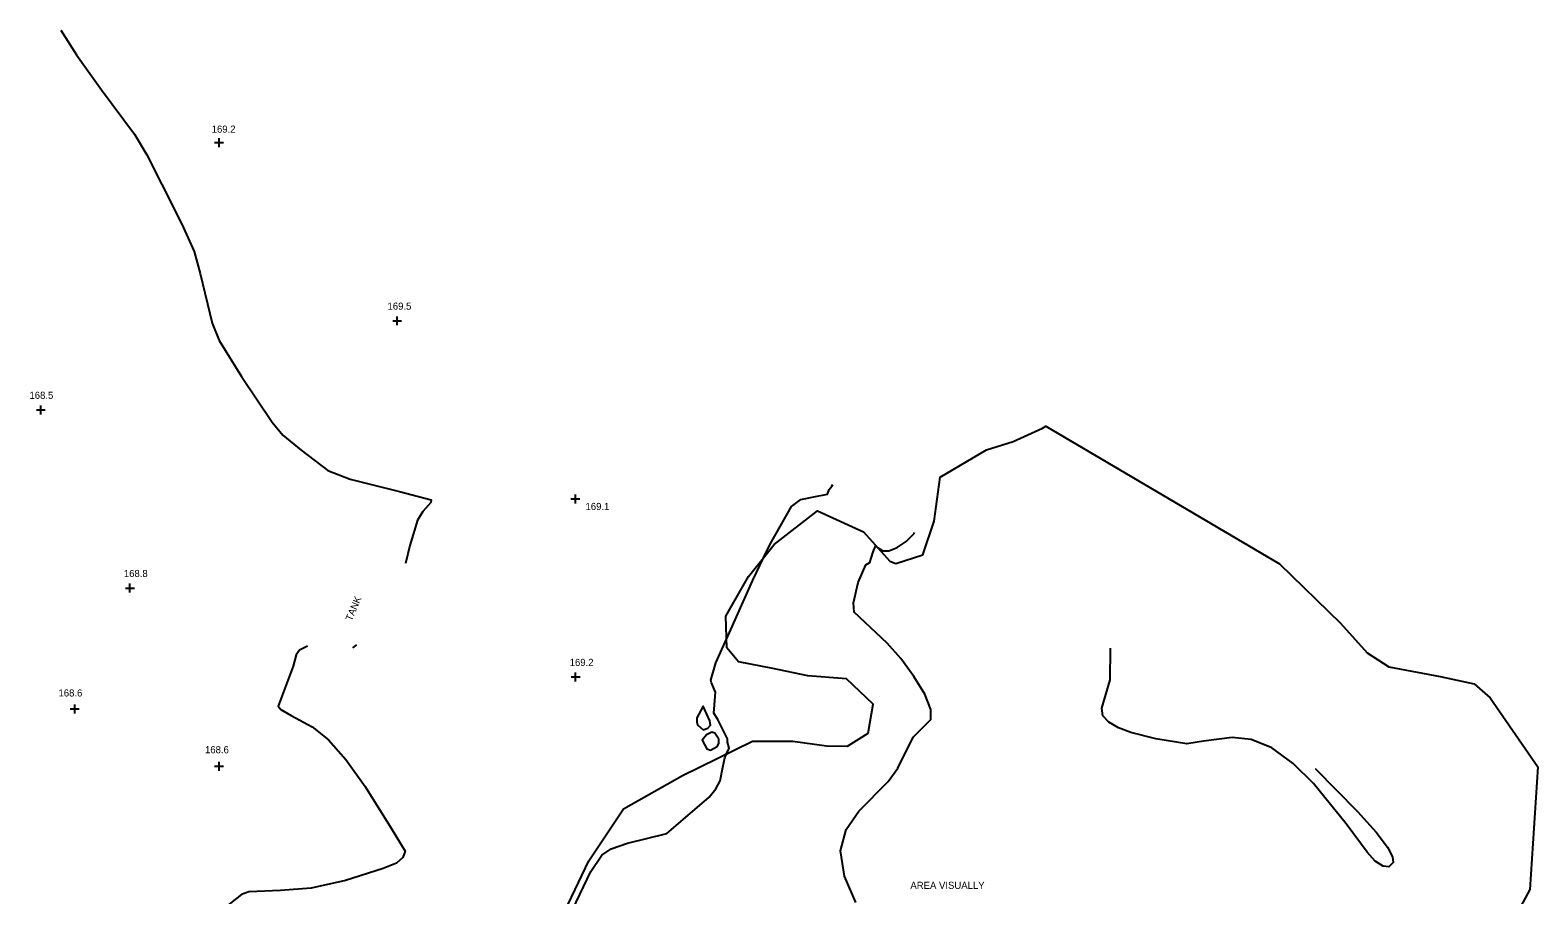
# Model space of a CAD drawing. Extents: x 1467615 to 2003689, y 770235 to 1108726.
# Drawn here: x 1998722 to 1999145.1, y 775913.9 to 776156.6 of the extents above; entities that cross this region are included whole.
import ezdxf

# ---------------------------------------------------------------- set-up
doc = ezdxf.new("R2010")
doc.units = 0
for name, color, linetype in [('RD_DTM_Major1', 7, 'Continuous'), ('RD_DTM_Minor1', 7, 'Continuous'), ('RD_DTM_Minor2', 7, 'Continuous'), ('RD_DTM_Obscure', 7, 'Continuous'), ('RD_DTM_Spot_Elev', 7, 'Continuous'), ('RD_TX_Misc1', 7, 'Continuous')]:
    doc.layers.add(name, color=color, linetype=linetype)

msp = doc.modelspace()

# ---------------------------------------------------------------- linework, layer by layer
at = {"layer": 'RD_DTM_Major1'}
for points in [[(1998909.08, 775962.46), (1998909.3, 775961.64), (1998910.88, 775960.23), (1998912.16, 775960.66), (1998912.92, 775961.54), (1998912.68, 775962.71), (1998910.89, 775966.9), (1998909.11, 775963.62), (1998909.08, 775962.46)], [(1998915.27, 775957.56), (1998914.14, 775959.25), (1998913.26, 775959.55), (1998911.76, 775958.82), (1998910.6, 775957.29), (1998911.89, 775954.92), (1998912.95, 775954.55), (1998914.81, 775955.51), (1998915.24, 775956.41), (1998915.27, 775957.56)]]:
    msp.add_lwpolyline(points, dxfattribs=at)
at = {"layer": 'RD_DTM_Minor1'}
for points in [[(1998730.64, 776156.56), (1998735.03, 776149.62), (1998741.99, 776139.85), (1998751.28, 776127.36), (1998754.76, 776121.6), (1998758.98, 776113.25), (1998764.59, 776102.1), (1998768.02, 776094.48), (1998769.75, 776088.23), (1998773.08, 776074.3), (1998775.08, 776069.49), (1998781.31, 776059.37), (1998789.91, 776046.55), (1998792.93, 776042.93), (1998798.05, 776038.7), (1998805.58, 776033.01), (1998811.79, 776030.52), (1998825.63, 776027.1), (1998834.53, 776024.74), (1998834.43, 776024.05), (1998832.16, 776021.45), (1998830.73, 776019.06), (1998828.52, 776011.95), (1998827.29, 776006.87)], [(1998927.8, 776008.52), (1998929.61, 776012.33), (1998935.68, 776022.86), (1998938.3, 776024.87), (1998941.92, 776025.64), (1998945.7, 776026.4), (1998946.23, 776027.65), (1998946.97, 776028.61), (1998947.22, 776029.05)], [(1998959.81, 776011.36), (1998961.28, 776010.43), (1998962.92, 776010.45), (1998965.25, 776011.36), (1998967.8, 776013.06), (1998970.02, 776015.36), (1998970.12, 776015.57)], [(1998917.38, 775953.46), (1998918.1, 775955.1), (1998917.72, 775956.74), (1998917.69, 775957.67), (1998915.78, 775961.48), (1998914.97, 775963.15), (1998913.84, 775964.94), (1998914.34, 775970.75), (1998913.19, 775973.45), (1998912.99, 775974.13), (1998914.39, 775978.98), (1998917.42, 775985.71)], [(1998799.86, 775983.7), (1998797.56, 775982.62), (1998796.67, 775981.26), (1998795.84, 775978.06), (1998791.62, 775966.89), (1998792.32, 775965.93), (1998795.26, 775964.29), (1998801.11, 775961.09), (1998805.73, 775957.39), (1998810.59, 775951.92), (1998815.97, 775944.28), (1998823.34, 775932.67), (1998827.22, 775926.18), (1998826.59, 775924.41), (1998824.81, 775922.84), (1998821.08, 775921.34), (1998810.47, 775917.93), (1998800.87, 775915.75), (1998792.24, 775915.18), (1998783.34, 775914.8), (1998781.34, 775914.03), (1998776.95, 775910.59)], [(1998813.57, 775984.1), (1998813.22, 775983.75), (1998812.5, 775983.19)]]:
    msp.add_lwpolyline(points, dxfattribs=at)
at = {"layer": 'RD_DTM_Minor2'}
for points in [[(1998953.66, 775911.79), (1998950.51, 775919.19), (1998949.39, 775926.23), (1998951, 775932.26), (1998954.55, 775937.36), (1998962.8, 775945.75), (1998965.46, 775949.49), (1998969.74, 775958.13), (1998974.74, 775963.11), (1998974.74, 775965.97), (1998973.02, 775970.19), (1998970, 775975.21), (1998966.28, 775980.26), (1998962.46, 775984.56), (1998953.21, 775993.26), (1998953.02, 775995.82), (1998954.32, 776001.59), (1998956.5, 776006.56), (1998957.65, 776007.22), (1998958.59, 776010.21), (1998959.23, 776011.72), (1998959.81, 776011.36)], [(1998917.42, 775985.71), (1998919.49, 775990.29), (1998924.8, 776002.19), (1998927.8, 776008.52)], [(1999082.57, 775949.37), (1999094.49, 775937.32), (1999099.73, 775931.53), (1999102.91, 775927.33), (1999104.3, 775924.6), (1999104.47, 775922.99), (1999103.26, 775921.78), (1999101.67, 775921.96), (1999099.41, 775923.39), (1999097.17, 775925.92), (1999091.23, 775933.81), (1999082.06, 775945.12), (1999076.38, 775950.82), (1999070.46, 775955.18), (1999064.66, 775957.49), (1999059.3, 775958.11), (1999051.2, 775957.01), (1999046.59, 775956.25), (1999037.85, 775957.71), (1999030.83, 775959.52), (1999027.43, 775960.79), (1999024.68, 775962.34), (1999023.03, 775964.19), (1999022.74, 775966.35), (1999025.01, 775974.25), (1999025.12, 775983.03), (1999025.19, 775983.15)], [(1998870.85, 775901.6), (1998875.18, 775911.85), (1998879.32, 775920.48), (1998882.46, 775925.06), (1998885.06, 775926.84), (1998889.58, 775928.44), (1998900.61, 775931.17), (1998905.2, 775935.03), (1998912.52, 775941.35), (1998914.45, 775943.66), (1998915.61, 775945.89), (1998916.4, 775949.79), (1998916.89, 775952.36), (1998917.38, 775953.46)]]:
    msp.add_lwpolyline(points, dxfattribs=at)
at = {"layer": 'RD_DTM_Obscure'}
for points in [[(1998872.93, 775911.34), (1998878.75, 775923.44), (1998888.53, 775938.01), (1998905.09, 775947.43), (1998924.72, 775957.06), (1998935.99, 775957.02), (1998945.48, 775955.74), (1998951.39, 775955.61), (1998957.14, 775959.31), (1998958.53, 775967.46), (1998951.08, 775974.56), (1998940.22, 775975.34), (1998930.38, 775977.41), (1998920.73, 775979.27), (1998917.5, 775983.27), (1998917.22, 775992.09), (1998923.56, 776003.22), (1998930.74, 776012.2), (1998942.93, 776021.68), (1998955.81, 776015.81), (1998963.21, 776007.56), (1998964.9, 776006.89), (1998972.5, 776009.35), (1998975.69, 776018.75), (1998977.32, 776031.12), (1998990.39, 776038.84), (1998997.8, 776041.12), (1999006.05, 776044.89), (1999007.04, 776045.41), (1999072.6, 776006.76), (1999089.72, 775990.11), (1999097.13, 775981.85), (1999103.24, 775977.88), (1999117.66, 775975.17), (1999127.14, 775973.12), (1999131.72, 775969.23), (1999145.05, 775949.81)], [(1999145.05, 775949.81), (1999142.8, 775915.4), (1999133.63, 775898.44)]]:
    msp.add_lwpolyline(points, dxfattribs=at)
at = {"layer": 'RD_DTM_Spot_Elev'}
for p, q in [((1998773.75, 776125), (1998776.25, 776125)), ((1998775, 776123.75), (1998775, 776126.25)), ((1998823.75, 776075), (1998826.25, 776075)), ((1998825, 776073.75), (1998825, 776076.25)), ((1998723.75, 776050), (1998726.25, 776050)), ((1998725, 776048.75), (1998725, 776051.25)), ((1998873.75, 776025), (1998876.25, 776025)), ((1998875, 776023.75), (1998875, 776026.25)), ((1998748.75, 776000), (1998751.25, 776000)), ((1998750, 775998.75), (1998750, 776001.25)), ((1998875.05, 775973.8), (1998875.05, 775976.3)), ((1998873.8, 775975.05), (1998876.3, 775975.05)), ((1998733.28, 775966.1), (1998735.78, 775966.1)), ((1998734.53, 775964.85), (1998734.53, 775967.35)), ((1998775, 775948.75), (1998775, 775951.25)), ((1998773.75, 775950), (1998776.25, 775950))]:
    msp.add_line(p, q, dxfattribs=at)

# ---------------------------------------------------------------- texts
for s, p in [('169.2', (1998772.95, 776127.79)), ('169.5', (1998822.28, 776078.12)), ('168.5', (1998721.81, 776053.1)), ('169.1', (1998877.84, 776021.91)), ('168.8', (1998748.3, 776003.1)), ('169.2', (1998873.4, 775978.15)), ('168.6', (1998729.96, 775969.58)), ('168.6', (1998771.07, 775953.65))]:
    msp.add_text(s, height=2, dxfattribs=at).set_placement(p)
at = {"layer": 'RD_TX_Misc1'}
msp.add_text('TANK', height=2, rotation=67.1268, dxfattribs=at).set_placement((1998812.25, 775990.59))
msp.add_text('AREA VISUALLY', height=2, dxfattribs=at).set_placement((1998969, 775915.59))

doc.saveas('drawing.dxf')
